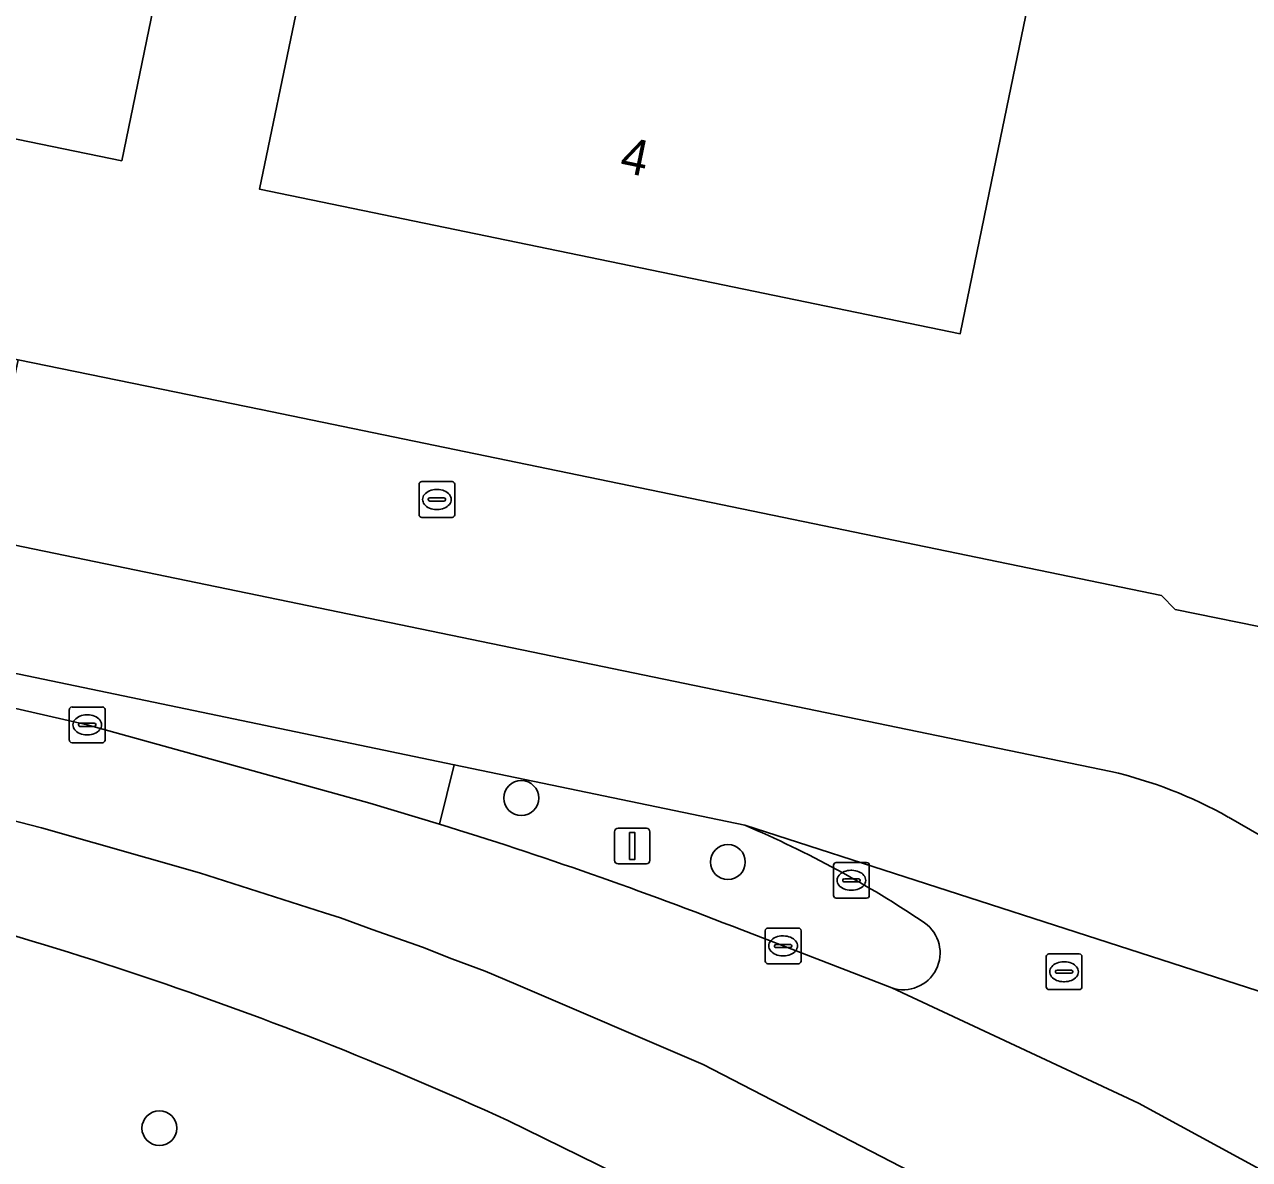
# Model space of a CAD drawing. Extents: x 157692 to 159674, y 381452 to 383291.
# Drawn here: x 158779.28 to 158813.59, y 382064.61 to 382096.4 of the extents above; entities that cross this region are included whole.
import ezdxf

# ---------------------------------------------------------------- set-up
doc = ezdxf.new("R2010")
doc.units = 0
for name, color, linetype in [('IMGEO_Berm_groen', 7, 'Continuous'), ('IMGEO_Berm_open', 7, 'Continuous'), ('IMGEO_Boom', 7, 'Continuous'), ('IMGEO_Brandkraan', 7, 'Continuous'), ('IMGEO_Erf', 7, 'Continuous'), ('IMGEO_Fietspad_gesloten', 7, 'Continuous'), ('IMGEO_Kolk', 7, 'Continuous'), ('IMGEO_Lichtmast', 7, 'Continuous'), ('IMGEO_Pand', 7, 'Continuous'), ('IMGEO_Pand_nummerreeks', 7, 'Continuous'), ('IMGEO_Rijbaan_lokaal_open', 7, 'Continuous'), ('IMGEO_Rijbaan_regionaal_gesloten', 7, 'Continuous'), ('IMGEO_Rioolput', 7, 'Continuous'), ('IMGEO_Verkeerseiland_groen', 7, 'Continuous')]:
    doc.layers.add(name, color=color, linetype=linetype)

msp = doc.modelspace()

# ---------------------------------------------------------------- linework, layer by layer
at = {"layer": 'IMGEO_Berm_groen'}
msp.add_lwpolyline([(158795.847, 382064.219), (158792.814, 382065.702)], dxfattribs=at)
msp.add_arc((158749.046, 381969.81), 105.408, 65.46642, 77.85955, dxfattribs=at)
at = {"layer": 'IMGEO_Berm_open'}
msp.add_lwpolyline([(158640.25, 382105.785), (158773.962, 382078.399), (158781.033, 382076.781), (158788.955, 382074.588), (158790.901, 382074.003), (158791.317, 382075.663), (158759.226, 382082.344), (158640.458, 382106.746)], dxfattribs=at)
at = {"layer": 'IMGEO_Boom'}
for centre in [(158793.194, 382074.731), (158798.981, 382072.938), (158783.056, 382065.485)]:
    msp.add_circle(centre, 0.489, dxfattribs=at)
at = {"layer": 'IMGEO_Brandkraan'}
for p, q in [((158790.404, 382083.593), (158791.256, 382083.593)), ((158790.329, 382082.667), (158790.329, 382083.519)), ((158790.817, 382083.373), (158790.842, 382083.373)), ((158791.33, 382083.519), (158791.33, 382082.667)), ((158790.588, 382083.087), (158790.588, 382083.099)), ((158791.026, 382083.05), (158790.628, 382083.05)), ((158790.631, 382083.136), (158791.029, 382083.136)), ((158791.072, 382083.099), (158791.072, 382083.087)), ((158791.256, 382082.593), (158790.404, 382082.593)), ((158790.84, 382082.813), (158790.815, 382082.813))]:
    msp.add_line(p, q, dxfattribs=at)
for points in [[(158790.404, 382083.593), (158791.256, 382083.593)], [(158790.329, 382082.667), (158790.329, 382083.519)], [(158791.33, 382083.519), (158791.33, 382082.667)], [(158791.256, 382082.593), (158790.404, 382082.593)]]:
    msp.add_lwpolyline(points, dxfattribs=at)
for centre, radius, start, end in [((158790.406, 382083.517), 0.0765, 91.552, 178.448), ((158790.406, 382083.517), 0.0765, 91.552, 178.448), ((158791.254, 382083.517), 0.0765, 1.552, 88.448), ((158791.254, 382083.517), 0.0765, 1.552, 88.448), ((158790.628, 382083.096), 0.0403, 85.8775, 175.7526), ((158790.625, 382083.086), 0.0366, 178.938, 274.7102), ((158791.029, 382083.093), 0.043, 264.8664, 352.4533), ((158791.033, 382083.098), 0.0386, 1.7309, 96.639), ((158790.406, 382082.669), 0.0765, 181.552, 268.448), ((158790.406, 382082.669), 0.0765, 181.552, 268.448), ((158791.254, 382082.669), 0.0765, 271.552, 358.448), ((158791.254, 382082.669), 0.0765, 271.552, 358.448)]:
    msp.add_arc(centre, radius, start, end, dxfattribs=at)
for centre, major_axis, ratio, start_param, end_param in [((158790.816, 382083.093), (-0.387, 0.002), 0.722429, 4.712389, 7.853982), ((158790.841, 382083.093), (-0.39, 0.002), 0.717154, 1.570796, 4.712389)]:
    msp.add_ellipse(centre, major_axis=major_axis, ratio=ratio, start_param=start_param, end_param=end_param, dxfattribs=at)
at = {"layer": 'IMGEO_Erf'}
msp.add_lwpolyline([(158765.247, 382235.426), (158752.653, 382174.095), (158746.409, 382143.691), (158738.086, 382103.16), (158737.08, 382098.262), (158736.964, 382098.286), (158733.679, 382098.961), (158733.173, 382096.498), (158736.463, 382095.809), (158737.882, 382095.512), (158747.563, 382093.491), (158779.094, 382087.008), (158785.901, 382085.615), (158811.125, 382080.406), (158811.515, 382080.009), (158814.452, 382079.413), (158814.541, 382079.95), (158831.712, 382076.46), (158832.164, 382078.78), (158855.441, 382074.005)], dxfattribs=at)
for points in [[(158786.877, 382096.681), (158793.965, 382130.94), (158813.573, 382126.911), (158806.501, 382092.632), (158805.491, 382087.735), (158785.864, 382091.784)], [(158786.796, 382115.911), (158783.008, 382097.477), (158782.001, 382092.579), (158764.114, 382096.257), (158764.263, 382096.981), (158762.098, 382097.428), (158761.948, 382096.702), (158749.361, 382099.29), (158750.384, 382104.185), (158754.21, 382122.499)]]:
    msp.add_lwpolyline(points, close=True, dxfattribs=at)
at = {"layer": 'IMGEO_Fietspad_gesloten'}
for points in [[(158551.776, 382125.053), (158552.592, 382124.924), (158589.111, 382118.343), (158593.588, 382117.233), (158601.914, 382114.691), (158606.841, 382113.579), (158610.985, 382112.743), (158640.458, 382106.746), (158759.226, 382082.344), (158791.317, 382075.663), (158799.46, 382073.968), (158814.721, 382069.044), (158815.071, 382068.931), (158816.815, 382072.002), (158813.002, 382074.196)], [(158809.708, 382075.476), (158712.956, 382095.452), (158620.94, 382114.323)]]:
    msp.add_lwpolyline(points, dxfattribs=at)
msp.add_arc((158806.913, 382063.406), 12.39, 60.5652, 76.964, dxfattribs=at)
at = {"layer": 'IMGEO_Kolk'}
for p, q in [((158780.532, 382076.355), (158780.532, 382077.207)), ((158780.607, 382077.281), (158781.459, 382077.281)), ((158781.02, 382077.061), (158781.045, 382077.061)), ((158781.533, 382077.207), (158781.533, 382076.355)), ((158780.791, 382076.775), (158780.791, 382076.787)), ((158781.229, 382076.738), (158780.831, 382076.738)), ((158780.834, 382076.824), (158781.232, 382076.824)), ((158781.275, 382076.787), (158781.275, 382076.775)), ((158781.043, 382076.501), (158781.018, 382076.501)), ((158781.459, 382076.281), (158780.607, 382076.281)), ((158802.017, 382072.927), (158802.869, 382072.927)), ((158801.942, 382072.001), (158801.942, 382072.853)), ((158802.43, 382072.707), (158802.455, 382072.707)), ((158802.943, 382072.853), (158802.943, 382072.001)), ((158802.201, 382072.421), (158802.201, 382072.433)), ((158802.639, 382072.384), (158802.241, 382072.384)), ((158802.244, 382072.47), (158802.642, 382072.47)), ((158802.685, 382072.433), (158802.685, 382072.421)), ((158802.869, 382071.927), (158802.017, 382071.927)), ((158802.453, 382072.147), (158802.428, 382072.147)), ((158800.029, 382070.164), (158800.029, 382071.016)), ((158800.104, 382071.09), (158800.956, 382071.09)), ((158800.517, 382070.87), (158800.542, 382070.87)), ((158801.03, 382071.016), (158801.03, 382070.164)), ((158800.288, 382070.584), (158800.288, 382070.596)), ((158800.726, 382070.547), (158800.328, 382070.547)), ((158800.331, 382070.633), (158800.729, 382070.633)), ((158800.772, 382070.596), (158800.772, 382070.584)), ((158800.54, 382070.31), (158800.515, 382070.31)), ((158800.956, 382070.09), (158800.104, 382070.09))]:
    msp.add_line(p, q, dxfattribs=at)
for points in [[(158780.532, 382076.355), (158780.532, 382077.207)], [(158780.607, 382077.281), (158781.459, 382077.281)], [(158781.533, 382077.207), (158781.533, 382076.355)], [(158781.459, 382076.281), (158780.607, 382076.281)], [(158802.017, 382072.927), (158802.869, 382072.927)], [(158801.942, 382072.001), (158801.942, 382072.853)], [(158802.943, 382072.853), (158802.943, 382072.001)], [(158802.869, 382071.927), (158802.017, 382071.927)], [(158800.029, 382070.164), (158800.029, 382071.016)], [(158800.104, 382071.09), (158800.956, 382071.09)], [(158801.03, 382071.016), (158801.03, 382070.164)], [(158800.956, 382070.09), (158800.104, 382070.09)]]:
    msp.add_lwpolyline(points, dxfattribs=at)
for centre, radius, start, end in [((158780.609, 382077.205), 0.0765, 91.552, 178.448), ((158780.609, 382077.205), 0.0765, 91.552, 178.448), ((158781.457, 382077.205), 0.0765, 1.552, 88.448), ((158781.457, 382077.205), 0.0765, 1.552, 88.448), ((158780.831, 382076.784), 0.0403, 85.8775, 175.7526), ((158780.828, 382076.774), 0.0366, 178.938, 274.7102), ((158781.232, 382076.781), 0.043, 264.8664, 352.4533), ((158781.236, 382076.786), 0.0386, 1.7309, 96.639), ((158780.609, 382076.357), 0.0765, 181.552, 268.448), ((158780.609, 382076.357), 0.0765, 181.552, 268.448), ((158781.457, 382076.357), 0.0765, 271.552, 358.448), ((158781.457, 382076.357), 0.0765, 271.552, 358.448), ((158802.019, 382072.851), 0.0765, 91.552, 178.448), ((158802.019, 382072.851), 0.0765, 91.552, 178.448), ((158802.867, 382072.851), 0.0765, 1.552, 88.448), ((158802.867, 382072.851), 0.0765, 1.552, 88.448), ((158802.241, 382072.43), 0.0403, 85.8775, 175.7526), ((158802.238, 382072.42), 0.0366, 178.938, 274.7102), ((158802.642, 382072.427), 0.043, 264.8664, 352.4533), ((158802.646, 382072.432), 0.0386, 1.7309, 96.639), ((158802.019, 382072.003), 0.0765, 181.552, 268.448), ((158802.019, 382072.003), 0.0765, 181.552, 268.448), ((158802.867, 382072.003), 0.0765, 271.552, 358.448), ((158802.867, 382072.003), 0.0765, 271.552, 358.448), ((158800.106, 382071.014), 0.0765, 91.552, 178.448), ((158800.106, 382071.014), 0.0765, 91.552, 178.448), ((158800.954, 382071.014), 0.0765, 1.552, 88.448), ((158800.954, 382071.014), 0.0765, 1.552, 88.448), ((158800.328, 382070.593), 0.0403, 85.8775, 175.7526), ((158800.325, 382070.583), 0.0366, 178.938, 274.7102), ((158800.729, 382070.59), 0.043, 264.8664, 352.4533), ((158800.733, 382070.595), 0.0386, 1.7309, 96.639), ((158800.106, 382070.166), 0.0765, 181.552, 268.448), ((158800.106, 382070.166), 0.0765, 181.552, 268.448), ((158800.954, 382070.166), 0.0765, 271.552, 358.448), ((158800.954, 382070.166), 0.0765, 271.552, 358.448)]:
    msp.add_arc(centre, radius, start, end, dxfattribs=at)
for centre, major_axis, ratio, start_param, end_param in [((158781.019, 382076.781), (-0.387, 0.002), 0.722429, 4.712389, 7.853982), ((158781.044, 382076.781), (-0.39, 0.002), 0.717154, 1.570796, 4.712389), ((158802.429, 382072.427), (-0.387, 0.002), 0.722429, 4.712389, 7.853982), ((158802.454, 382072.427), (-0.39, 0.002), 0.717154, 1.570796, 4.712389), ((158800.516, 382070.59), (-0.387, 0.002), 0.722429, 4.712389, 7.853982), ((158800.541, 382070.59), (-0.39, 0.002), 0.717154, 1.570796, 4.712389)]:
    msp.add_ellipse(centre, major_axis=major_axis, ratio=ratio, start_param=start_param, end_param=end_param, dxfattribs=at)
at = {"layer": 'IMGEO_Lichtmast'}
for p, q in [((158795.807, 382072.987), (158795.807, 382073.787)), ((158795.807, 382073.787), (158795.807, 382072.987)), ((158795.907, 382073.887), (158796.697, 382073.887)), ((158796.697, 382073.887), (158795.907, 382073.887)), ((158796.797, 382073.787), (158796.797, 382072.987)), ((158796.797, 382072.987), (158796.797, 382073.787)), ((158796.697, 382072.887), (158795.907, 382072.887)), ((158795.907, 382072.887), (158796.697, 382072.887))]:
    msp.add_line(p, q, dxfattribs=at)
msp.add_lwpolyline([(158796.227, 382073.762), (158796.377, 382073.762), (158796.377, 382073.012), (158796.227, 382073.012), (158796.227, 382073.762)], dxfattribs=at)
for centre, start, end in [((158795.907, 382073.787), 90, 180), ((158795.907, 382073.787), 90, 180), ((158796.697, 382073.787), 0, 90), ((158796.697, 382073.787), 360, 90), ((158795.907, 382072.987), 180, 270), ((158795.907, 382072.987), 180, 270), ((158796.697, 382072.987), 270, 0), ((158796.697, 382072.987), 270, 0)]:
    msp.add_arc(centre, 0.1, start, end, dxfattribs=at)
at = {"layer": 'IMGEO_Pand'}
for points in [[(158786.877, 382096.681), (158785.864, 382091.784), (158805.491, 382087.735), (158806.501, 382092.632), (158813.573, 382126.911), (158793.965, 382130.94)], [(158764.114, 382096.257), (158782.001, 382092.579), (158783.008, 382097.477), (158786.796, 382115.911), (158754.21, 382122.499), (158750.384, 382104.185), (158749.361, 382099.29), (158761.948, 382096.702), (158762.098, 382097.428), (158764.263, 382096.981)]]:
    msp.add_lwpolyline(points, close=True, dxfattribs=at)
at = {"layer": 'IMGEO_Rijbaan_lokaal_open'}
for points in [[(158665.285, 382106.51), (158663.872, 382108.691), (158663.137, 382108.85), (158652.528, 382111.031), (158652.814, 382112.789), (158633.042, 382116.888), (158629.645, 382117.616), (158629.259, 382115.706), (158620.94, 382114.323), (158712.956, 382095.452), (158809.708, 382075.476)], [(158827.936, 382068.2), (158828.413, 382068.102), (158829.393, 382072.876), (158854.168, 382067.855), (158855.441, 382074.005), (158832.164, 382078.78), (158831.712, 382076.46), (158814.541, 382079.95), (158814.452, 382079.413), (158811.515, 382080.009), (158811.125, 382080.406), (158785.901, 382085.615), (158779.094, 382087.008), (158778.693, 382085.11), (158774.926, 382085.873), (158751.126, 382090.777), (158747.156, 382091.589), (158747.563, 382093.491)], [(158813.002, 382074.196), (158816.815, 382072.002), (158827.317, 382065.961)]]:
    msp.add_lwpolyline(points, dxfattribs=at)
msp.add_arc((158806.913, 382063.406), 12.39, 60.5652, 76.964, dxfattribs=at)
at = {"layer": 'IMGEO_Rijbaan_regionaal_gesloten'}
for points in [[(158790.901, 382074.003), (158788.955, 382074.588), (158781.033, 382076.781), (158773.962, 382078.399), (158640.25, 382105.785), (158636.724, 382106.498), (158626.876, 382108.256), (158611.845, 382110.657), (158607.095, 382111.336), (158605.115, 382111.751), (158602.963, 382112.362), (158591.784, 382115.861)], [(158638.613, 382103.052), (158678.367, 382094.92), (158725.181, 382085.35), (158768.722, 382076.412), (158771.698, 382075.766), (158775.501, 382074.941), (158778.255, 382074.275), (158779.753, 382073.898), (158784.175, 382072.638), (158787.681, 382071.52), (158788.126, 382071.378), (158789.016, 382071.05), (158790.426, 382070.553), (158791.247, 382070.227), (158792.18, 382069.883), (158793.04, 382069.515), (158798.29, 382067.268), (158812.129, 382060.118), (158819.626, 382060.97), (158813.88, 382064.337), (158810.482, 382066.189), (158803.572, 382069.414), (158799.374, 382071.037)], [(158803.486, 382059.437), (158803.878, 382059.18), (158812.129, 382060.118), (158798.29, 382067.268), (158793.04, 382069.515), (158792.18, 382069.883), (158791.247, 382070.227), (158790.426, 382070.553), (158789.016, 382071.05), (158788.126, 382071.378), (158787.681, 382071.52), (158784.175, 382072.638), (158779.753, 382073.898), (158778.255, 382074.275), (158775.501, 382074.941), (158771.698, 382075.766), (158768.722, 382076.412), (158725.181, 382085.35), (158678.367, 382094.92), (158638.613, 382103.052)], [(158814.721, 382069.044), (158799.46, 382073.968)], [(158803.572, 382069.414), (158810.482, 382066.189), (158813.88, 382064.337), (158819.626, 382060.97), (158820.295, 382061.046)], [(158792.814, 382065.702), (158795.847, 382064.219)]]:
    msp.add_lwpolyline(points, dxfattribs=at)
for centre, radius, start, end in [((158754.909, 381957.598), 121.842, 68.59604, 72.81845), ((158787.56, 382046.038), 30.36, 56.0982, 66.9236), ((158749.046, 381969.81), 105.408, 65.46642, 77.85955), ((158803.894, 382070.395), 1.033, 251.8077, 54.5101)]:
    msp.add_arc(centre, radius, start, end, dxfattribs=at)
at = {"layer": 'IMGEO_Rioolput'}
for p, q in [((158807.9, 382069.44), (158807.9, 382070.292)), ((158807.975, 382070.366), (158808.827, 382070.366)), ((158808.901, 382070.292), (158808.901, 382069.44)), ((158808.159, 382069.86), (158808.159, 382069.872)), ((158808.202, 382069.909), (158808.6, 382069.909)), ((158808.388, 382070.146), (158808.413, 382070.146)), ((158808.643, 382069.872), (158808.643, 382069.86)), ((158808.597, 382069.823), (158808.199, 382069.823)), ((158808.411, 382069.586), (158808.386, 382069.586)), ((158808.827, 382069.366), (158807.975, 382069.366))]:
    msp.add_line(p, q, dxfattribs=at)
for points in [[(158807.9, 382069.44), (158807.9, 382070.292)], [(158807.975, 382070.366), (158808.827, 382070.366)], [(158808.901, 382070.292), (158808.901, 382069.44)], [(158808.827, 382069.366), (158807.975, 382069.366)]]:
    msp.add_lwpolyline(points, dxfattribs=at)
for centre, radius, start, end in [((158807.977, 382070.29), 0.0765, 91.552, 178.448), ((158807.977, 382070.29), 0.0765, 91.552, 178.448), ((158808.825, 382070.29), 0.0765, 1.552, 88.448), ((158808.825, 382070.29), 0.0765, 1.552, 88.448), ((158808.199, 382069.869), 0.0403, 85.8775, 175.7526), ((158808.196, 382069.859), 0.0366, 178.938, 274.7102), ((158808.6, 382069.866), 0.043, 264.8664, 352.4533), ((158808.604, 382069.871), 0.0386, 1.7309, 96.639), ((158807.977, 382069.442), 0.0765, 181.552, 268.448), ((158807.977, 382069.442), 0.0765, 181.552, 268.448), ((158808.825, 382069.442), 0.0765, 271.552, 358.448), ((158808.825, 382069.442), 0.0765, 271.552, 358.448)]:
    msp.add_arc(centre, radius, start, end, dxfattribs=at)
for centre, major_axis, ratio, start_param, end_param in [((158808.387, 382069.866), (-0.387, 0.002), 0.722429, 4.712389, 7.853982), ((158808.412, 382069.866), (-0.39, 0.002), 0.717154, 1.570796, 4.712389)]:
    msp.add_ellipse(centre, major_axis=major_axis, ratio=ratio, start_param=start_param, end_param=end_param, dxfattribs=at)
at = {"layer": 'IMGEO_Verkeerseiland_groen'}
for points in [[(158799.46, 382073.968), (158791.317, 382075.663), (158790.901, 382074.003)], [(158799.374, 382071.037), (158803.572, 382069.414)]]:
    msp.add_lwpolyline(points, dxfattribs=at)
for centre, radius, start, end in [((158754.909, 381957.598), 121.842, 68.59604, 72.81845), ((158787.56, 382046.038), 30.36, 56.0982, 66.9236), ((158803.894, 382070.395), 1.033, 251.8077, 54.5101)]:
    msp.add_arc(centre, radius, start, end, dxfattribs=at)

# ---------------------------------------------------------------- texts
at = {"layer": 'IMGEO_Pand_nummerreeks'}
msp.add_text('4', height=1, rotation=348.3436, dxfattribs=at).set_placement((158795.916, 382092.283))

doc.saveas('drawing.dxf')
